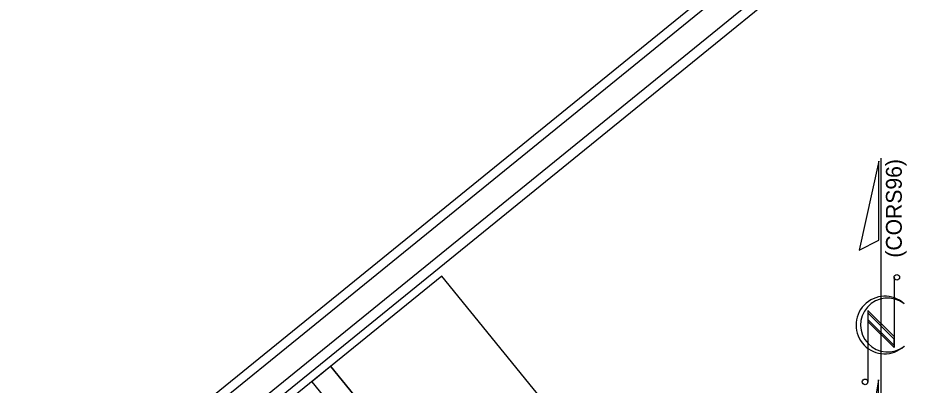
# Model space of a CAD drawing. Extents: x 2596486 to 2602076, y 851390 to 856110.
# Drawn here: x 2596486 to 2597258, y 853758 to 854076 of the extents above; entities that cross this region are included whole.
import ezdxf

# ---------------------------------------------------------------- set-up
doc = ezdxf.new("R2010")
doc.units = 0
for name, color, linetype in [('Old_Level_12', 7, 'Continuous'), ('Sheet North Arrow CELL', 7, 'Continuous'), ('Sheet Plot Border Inside CELL', 7, 'Continuous'), ('Sheet Plot Border Outside CELL', 7, 'Continuous'), ('Sheet Title CELL', 7, 'Continuous')]:
    doc.layers.add(name, color=color, linetype=linetype)

msp = doc.modelspace()

# ---------------------------------------------------------------- linework, layer by layer
at = {"layer": 'Old_Level_12'}
msp.add_lwpolyline([(2596756.38, 853774.59), (2597051.2, 853411.85), (2597147.31, 853489.97), (2596852.49, 853852.71)], close=True, dxfattribs=at)
at = {"layer": 'Sheet North Arrow CELL'}
for p, q in [((2597232.53, 853658.65), (2597232.53, 853954.8)), ((2597243.69, 853851.74), (2597243.69, 853790.96)), ((2597252.08, 853829.1), (2597252.4, 853828.87)), ((2597243.69, 853800.44), (2597221.05, 853823.08)), ((2597221.05, 853823.08), (2597221.05, 853761.3)), ((2597243.69, 853798.21), (2597221.05, 853820.85)), ((2597221.05, 853820.85), (2597221.05, 853815.29)), ((2597243.69, 853792.65), (2597221.05, 853815.29)), ((2597221.05, 853815.29), (2597243.69, 853792.65)), ((2597243.69, 853790.96), (2597221.05, 853813.61)), ((2597243.69, 853792.65), (2597243.69, 853798.21))]:
    msp.add_line(p, q, dxfattribs=at)
for points in [[(2597230.48, 853952.21), (2597213.58, 853875.3), (2597230.48, 853883.86)], [(2597230.12, 853762.99), (2597213.35, 853658.65), (2597230.12, 853671.86)]]:
    msp.add_lwpolyline(points, close=True, dxfattribs=at)
for centre in [(2597246.11, 853851.69), (2597218.64, 853761.21)]:
    msp.add_circle(centre, 2.41, dxfattribs=at)
for centre, radius, start, end in [((2597235.68, 853810.43), 24.88, 47.84002, 312.39406), ((2597238.09, 853810.44), 23.32, 53.09504, 308.62871)]:
    msp.add_arc(centre, radius, start, end, dxfattribs=at)
at = {"layer": 'Sheet Plot Border Inside CELL'}
msp.add_lwpolyline([(2599699.12, 852562.74), (2597912.27, 854761.23), (2596520.36, 853629.94), (2598307.2, 851431.45)], close=True, dxfattribs=at)
at = {"layer": 'Sheet Plot Border Outside CELL'}
msp.add_lwpolyline([(2596485.91, 853611.8), (2598291.52, 851390.23), (2599742.65, 852569.65), (2597937.05, 854791.22)], close=True, dxfattribs=at)
at = {"layer": 'Sheet Title CELL'}
for points in [[(2597909.1, 854731.27), (2596550.31, 853626.9)], [(2597663.83, 854520.97), (2596562.26, 853625.66)], [(2596854.84, 853653.8), (2596756.51, 853774.78), (2596558.63, 853613.94)], [(2597051.37, 853411.99), (2596756.51, 853774.78), (2596740.04, 853761.39), (2597034.88, 853398.59)]]:
    msp.add_lwpolyline(points, dxfattribs=at)

# ---------------------------------------------------------------- texts
at = {"layer": 'Sheet North Arrow CELL'}
msp.add_text('(CORS96)', height=13.669, rotation=90, dxfattribs=at).set_placement((2597250.36, 853868.75))

doc.saveas('drawing.dxf')
